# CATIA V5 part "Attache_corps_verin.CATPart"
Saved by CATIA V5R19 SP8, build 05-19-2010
Part number: Attache_corps_verin
Bounding box of the stored display mesh (mm): x -51.5 to 3, y -17.5 to 17.5, z -17.444 to 17.444
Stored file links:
  G:\EU_thinkMotion\CFAO_2010\MMS_groupe1\MMS_groupe1\OK\vduret\vduret\CATIA\Attache_corps_verin.CATPart
  F:\CFAO TP\Machine_de_coupe.CATProduct
  G:\EU_thinkMotion\CFAO_2010\MMS_groupe1\MMS_groupe1\OK\vduret\vduret\CATIA\Corps_Verin.CATPart
  G:\EU_thinkMotion\CFAO_2010\MMS_groupe1\MMS_groupe1\OK\vduret\vduret\CATIA\Tige_Verin.CATPart
  F:\CFAO_TP_fin\Machine_de_coupe_sans_geo.CATProduct
  G:\EU_thinkMotion\CFAO_2010\MMS_groupe1\MMS_groupe1\OK\vduret\vduret\CATIA\Profile_bati.CATPart
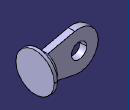
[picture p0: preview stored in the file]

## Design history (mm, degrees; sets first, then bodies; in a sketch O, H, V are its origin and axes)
External parameters (linked from other documents)
  External.Diam_corps_verin = 35 mm
  External.Diam_piston_verin = 30 mm
Body1 (main body)
  Sketch1 on yz-plane, origin (0, 0, 0), H (0, 1, 0), V (0, 0, 1)
    circle A1 centre (0, 0) radius 17.5
    radius A1 = 17.5 {= External.Diam_corps_verin /2}
  Pad1: profile Sketch1, direction (1, 0, 0), length 3
  Sketch2 on start face of Pad1, origin (0, 0, 0), H (0, -1, 0), V (0, 0, 1)
    circle A1 centre (0, 0) radius 12.5
    radius A1 = 12.5 {= External.Diam_corps_verin /2-5mm}
  Pad2: profile Sketch2, direction (-1, 0, 0), length 5
  Sketch3 on zx-plane, origin (0, 0, 0), H (-1, 0, 0), V (0, 0, 1)
    arc A1 centre (34, 0) radius 17.5 from (30.2151, -17.0858) to (30.2151, 17.0858) ccw
    point P1 (34, 0)
    line L1 (30.2151, 17.0858) -> (5, 11.5)
    point P2 (5, 11.5)
    line L2 (30.2151, -17.0858) -> (5, -11.5)
    point P3 (5, -11.5)
    reference projected line E1 (5, 12.5) -> (5, -12.5) from edge [face of Pad2 from Sketch2.A1 | end face of Pad2]
    reference projected line E2 (5, 12.5) -> (5, -12.5) from edge [face of Pad2 from Sketch2.A1 | end face of Pad2]
    reference projected line E3 (0, 12.5) -> (0, -12.5) from edge [start face of Pad1 | face of Pad2 from Sketch2.A1]
    circle A2 centre (34, 0) radius 7
    line L3 (5, 11.5) -> (5, -11.5)
    radius A1 = 17.5 {= External.Diam_corps_verin /2}
    distance P3 H = 11.5 {= External.Diam_corps_verin /2-6mm}
    distance P2 H = 11.5 {= External.Diam_corps_verin/2 -6mm}
    distance P1 E3 = 34
    radius A2 = 7
    coincidence: P1 H, P2 E1, P3 E2
    tangency: L2 A1, L1 A1
    vertical: L3 V
  Pad3: profile Sketch3, direction (0, 1, 0), length 3, mirrored extent
  Point1: type Center, Curve edge [face of Pad3 from Sketch3.A2 | start face of Pad3]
